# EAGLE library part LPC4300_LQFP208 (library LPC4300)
LQFP208 - SOT459-1 LQFP208: plastic low profile quad flat package; 208 leads; body 28 x 28 x 1.4 mm body + leads 30 x 30 mm Solderland (pads) 0.4 x 1.5 mm on corners (8 x) and 0.28 x 1.5 mm (200 x)
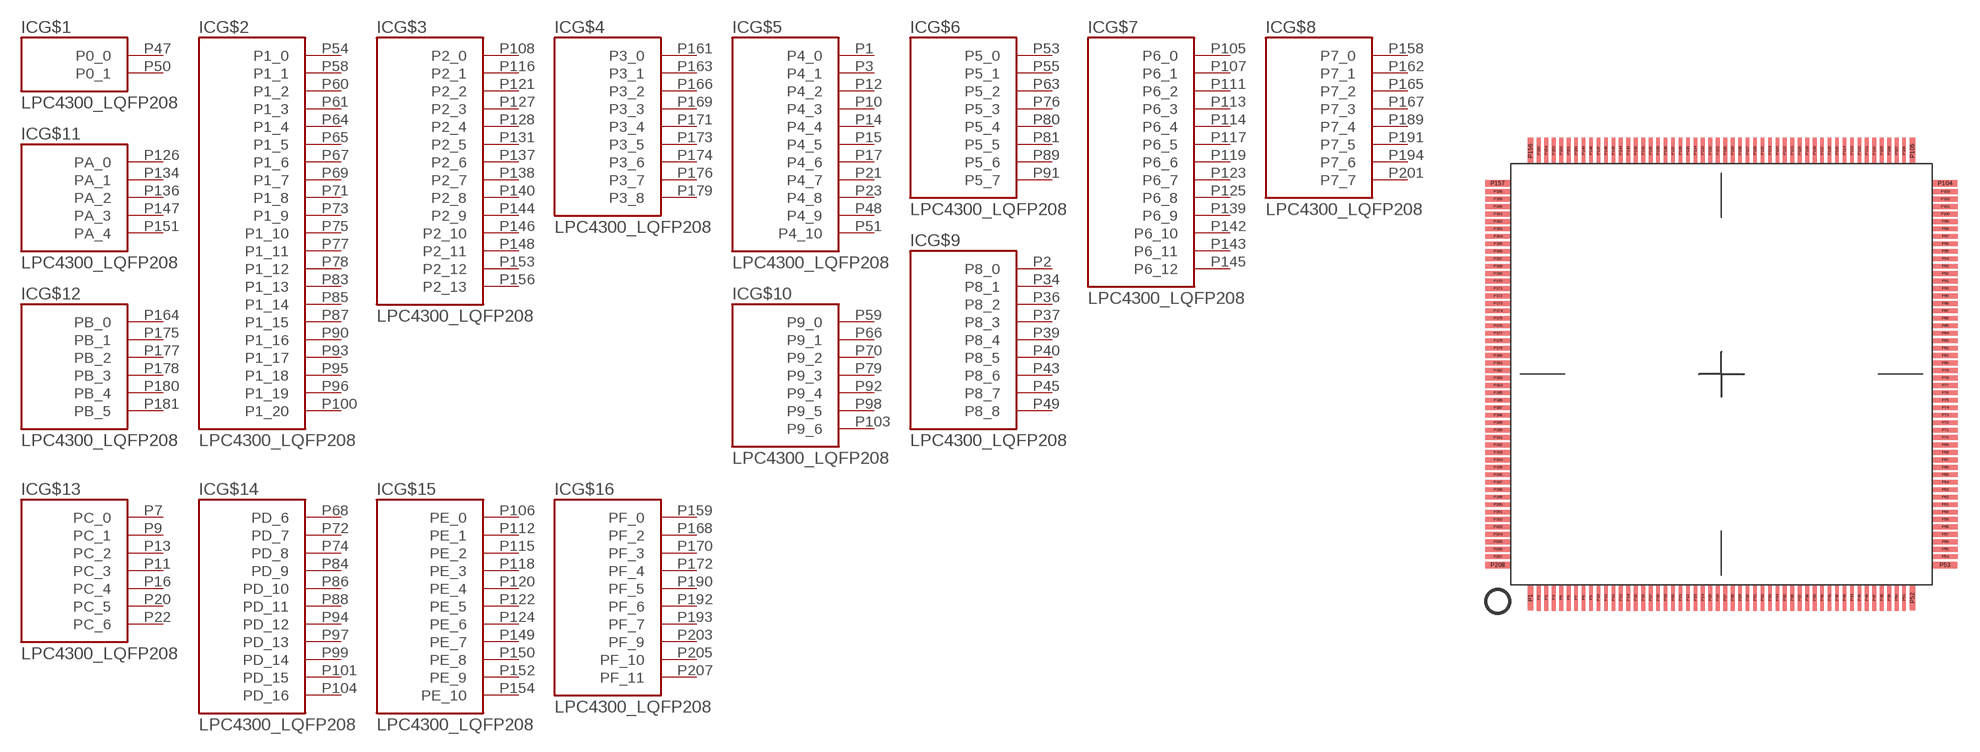
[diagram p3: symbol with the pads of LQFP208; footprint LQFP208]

Designator prefix IC; gates G$1=208_1_PORT0 G$2=208_2_PORT1 G$3=208_3_PORT2 G$4=208_4_PORT3 G$5=208_5_PORT4 G$6=208_6_PORT5 G$7=208_7_PORT6 G$8=208_8_PORT7 G$9=208_9_PORT8 G$10=208_10_PORT9 G$11=208_11_PORTA G$12=208_12_PORTB G$13=208_13_PORTC G$14=208_14_PORTD G$15=208_15_PORTE G$16=208_16_PORTF G$17=208_17_ANA G$18=208_18_RTC G$19=208_19_CLK G$20=208_20_DBUG G$21=208_21_I2C G$22=208_22_SUP G$23=208_23_USB

## LPC4300_LQFP208  [LQFP208]
P1  G$5:P4_0
P2  G$9:P8_0
P3  G$5:P4_1
P4  G$17:ADC1  in
P5  G$22:VSSIO1  sup
P6  G$22:VDDIO1  sup
P7  G$13:PC_0
P8  G$17:ADC0  in
P9  G$13:PC_1
P10  G$5:P4_3
P11  G$13:PC_3
P12  G$5:P4_2
P13  G$13:PC_2
P14  G$5:P4_4
P15  G$5:P4_5
P16  G$13:PC_4
P17  G$5:P4_6
P18  G$19:XTAL1  in
P19  G$19:XTAL2  out
P20  G$13:PC_5
P21  G$5:P4_7
P22  G$13:PC_6
P23  G$5:P4_8
P24  G$23:USB0_VDDA3V3_DRIVER
P25  G$23:USB0_VDDA3V3
P26  G$23:USB0_DP
P27  G$23:USB0_VSSA_TERM
P28  G$23:USB0_DM
P29  G$23:USB0_VBUS
P30  G$23:USB0_ID
P31  G$23:USB0_VSSA_REF
P32  G$23:USB0_RREF
P33  G$22:VDDREG5  sup
P34  G$9:P8_1
P35  G$20:TDI
P36  G$9:P8_2
P37  G$9:P8_3
P38  G$20:TCK
P39  G$9:P8_4
P40  G$9:P8_5
P41  G$20:DBGEN  in
P42  G$20:!TRST
P43  G$9:P8_6
P44  G$20:TMS
P45  G$9:P8_7
P46  G$20:TDO
P47  G$1:P0_0
P48  G$5:P4_9
P49  G$9:P8_8  sup
P50  G$1:P0_1
P51  G$5:P4_10
P52  G$22:VDDIO2  sup
P53  G$6:P5_0
P54  G$2:P1_0
P55  G$6:P5_1
P56  G$22:VSSIO2  sup
P57  G$22:VDDIO3  sup
P58  G$2:P1_1
P59  G$10:P9_0
P60  G$2:P1_2
P61  G$2:P1_3
P62  G$19:CLK0  out
P63  G$6:P5_2
P64  G$2:P1_4
P65  G$2:P1_5
P66  G$10:P9_1
P67  G$2:P1_6
P68  G$14:PD_6
P69  G$2:P1_7
P70  G$10:P9_2
P71  G$2:P1_8
P72  G$14:PD_7
P73  G$2:P1_9
P74  G$14:PD_8
P75  G$2:P1_10
P76  G$6:P5_3
P77  G$2:P1_11
P78  G$2:P1_12
P79  G$10:P9_3
P80  G$6:P5_4
P81  G$6:P5_5
P82  G$22:VDDREG4  sup
P83  G$2:P1_13
P84  G$14:PD_9
P85  G$2:P1_14
P86  G$14:PD_10
P87  G$2:P1_15
P88  G$14:PD_11
P89  G$6:P5_6
P90  G$2:P1_16
P91  G$6:P5_7
P92  G$10:P9_4
P93  G$2:P1_17
P94  G$14:PD_12
P95  G$2:P1_18
P96  G$2:P1_19
P97  G$14:PD_13
P98  G$10:P9_5
P99  G$14:PD_14
P100  G$2:P1_20
P101  G$14:PD_15
P102  G$22:VDDIO4  sup
P103  G$10:P9_6
P104  G$14:PD_16
P105  G$7:P6_0
P106  G$15:PE_0
P107  G$7:P6_1
P108  G$3:P2_0
P109  G$22:VSSIO3  sup
P110  G$22:VDDIO5  sup
P111  G$7:P6_2
P112  G$15:PE_1
P113  G$7:P6_3
P114  G$7:P6_4
P115  G$15:PE_2
P116  G$3:P2_1
P117  G$7:P6_5
P118  G$15:PE_3
P119  G$7:P6_6
P120  G$15:PE_4
P121  G$3:P2_2
P122  G$15:PE_5
P123  G$7:P6_7
P124  G$15:PE_6
P125  G$7:P6_8
P126  G$11:PA_0
P127  G$3:P2_3
P128  G$3:P2_4
P129  G$23:USB1_DP
P130  G$23:USB1_DM
P131  G$3:P2_5
P132  G$21:I2C0_SCL
P133  G$21:I2C0_SDA
P134  G$11:PA_1
P135  G$22:VDDREG1  sup
P136  G$11:PA_2
P137  G$3:P2_6
P138  G$3:P2_7
P139  G$7:P6_9
P140  G$3:P2_8
P141  G$19:CLK2  out
P142  G$7:P6_10
P143  G$7:P6_11
P144  G$3:P2_9
P145  G$7:P6_12
P146  G$3:P2_10
P147  G$11:PA_3
P148  G$3:P2_11
P149  G$15:PE_7
P150  G$15:PE_8
P151  G$11:PA_4
P152  G$15:PE_9
P153  G$3:P2_12
P154  G$15:PE_10
P155  G$22:VDDIO6  sup
P156  G$3:P2_13
P157  G$22:VSSIO4  sup
P158  G$8:P7_0
P159  G$16:PF_0
P160  G$22:VDDIO7  sup
P161  G$4:P3_0
P162  G$8:P7_1
P163  G$4:P3_1
P164  G$12:PB_0
P165  G$8:P7_2
P166  G$4:P3_2
P167  G$8:P7_3
P168  G$16:PF_2
P169  G$4:P3_3
P170  G$16:PF_3
P171  G$4:P3_4
P172  G$16:PF_4
P173  G$4:P3_5
P174  G$4:P3_6
P175  G$12:PB_1
P176  G$4:P3_7
P177  G$12:PB_2
P178  G$12:PB_3
P179  G$4:P3_8
P180  G$12:PB_4
P181  G$12:PB_5
P182  G$18:RTCX1  in
P183  G$18:RTCX2  out
P184  G$18:VBAT  pwr
P185  G$19:!RESET  in
P186  G$18:RTC_ALARM  out
P187  G$18:WAKEUP0  in
P188  G$22:VDDREG2  sup
P189  G$8:P7_4
P190  G$16:PF_5
P191  G$8:P7_5
P192  G$16:PF_6
P193  G$16:PF_7
P194  G$8:P7_6
P195  G$22:VDDREG3  sup
P196  G$17:VSSA  sup
P197  G$17:ADC7  in
P198  G$17:VDDA  sup
P199  G$17:ADC4  in
P200  G$17:ADC3  in
P201  G$8:P7_7
P202  G$22:VDDIO8  sup
P203  G$16:PF_9
P204  G$17:ADC6  in
P205  G$16:PF_10
P206  G$17:ADC2  in
P207  G$16:PF_11
P208  G$17:ADC5  in

## Footprint LQFP208 (pad centres in mm)
LQFP208 - SOT459-1 LQFP208: plastic low profile quad flat package; 208 leads; body 28 x 28 x 1.4 mm body + leads 30 x 30 mm Solderland (pads) 0.4 x 1.5 mm on corners (8 x) and 0.28 x 1.5 mm (200 x) .
smd 0.4 x 1.7: P1 -12.81,-15; P52 12.81,-15; P105 12.81,15; P156 -12.81,15
smd 0.28 x 1.7: P2 -12.25,-15; P3 -11.75,-15; P4 -11.25,-15; P5 -10.75,-15; P6 -10.25,-15; P7 -9.75,-15; P8 -9.25,-15; P9 -8.75,-15; P10 -8.25,-15; P11 -7.75,-15; P12 -7.25,-15; P13 -6.75,-15; P14 -6.25,-15; P15 -5.75,-15; P16 -5.25,-15; P17 -4.75,-15; P18 -4.25,-15; P19 -3.75,-15; P20 -3.25,-15; P21 -2.75,-15; P22 -2.25,-15; P23 -1.75,-15; P24 -1.25,-15; P25 -0.75,-15; P26 -0.25,-15; P27 0.25,-15; P28 0.75,-15; P29 1.25,-15; P30 1.75,-15; P31 2.25,-15; P32 2.75,-15; P33 3.25,-15; P34 3.75,-15; P35 4.25,-15; P36 4.75,-15; P37 5.25,-15; P38 5.75,-15; P39 6.25,-15; P40 6.75,-15; P41 7.25,-15; P42 7.75,-15; P43 8.25,-15; P44 8.75,-15; P45 9.25,-15; P46 9.75,-15; P47 10.25,-15; P48 10.75,-15; P49 11.25,-15; P50 11.75,-15; P51 12.25,-15; P106 12.25,15; P107 11.75,15; P108 11.25,15; P109 10.75,15; P110 10.25,15; P111 9.75,15; P112 9.25,15; P113 8.75,15; P114 8.25,15; P115 7.75,15; P116 7.25,15; P117 6.75,15; P118 6.25,15; P119 5.75,15; P120 5.25,15; P121 4.75,15; P122 4.25,15; P123 3.75,15; P124 3.25,15; P125 2.75,15; P126 2.25,15; P127 1.75,15; P128 1.25,15; P129 0.75,15; P130 0.25,15; P131 -0.25,15; P132 -0.75,15; P133 -1.25,15; P134 -1.75,15; P135 -2.25,15; P136 -2.75,15; P137 -3.25,15; P138 -3.75,15; P139 -4.25,15; P140 -4.75,15; P141 -5.25,15; P142 -5.75,15; P143 -6.25,15; P144 -6.75,15; P145 -7.25,15; P146 -7.75,15; P147 -8.25,15; P148 -8.75,15; P149 -9.25,15; P150 -9.75,15; P151 -10.25,15; P152 -10.75,15; P153 -11.25,15; P154 -11.75,15; P155 -12.25,15
smd 1.7 x 0.4: P53 15,-12.81; P104 15,12.81; P157 -15,12.81; P208 -15,-12.81
smd 1.7 x 0.28: P54 15,-12.25; P55 15,-11.75; P56 15,-11.25; P57 15,-10.75; P58 15,-10.25; P59 15,-9.75; P60 15,-9.25; P61 15,-8.75; P62 15,-8.25; P63 15,-7.75; P64 15,-7.25; P65 15,-6.75; P66 15,-6.25; P67 15,-5.75; P68 15,-5.25; P69 15,-4.75; P70 15,-4.25; P71 15,-3.75; P72 15,-3.25; P73 15,-2.75; P74 15,-2.25; P75 15,-1.75; P76 15,-1.25; P77 15,-0.75; P78 15,-0.25; P79 15,0.25; P80 15,0.75; P81 15,1.25; P82 15,1.75; P83 15,2.25; P84 15,2.75; P85 15,3.25; P86 15,3.75; P87 15,4.25; P88 15,4.75; P89 15,5.25; P90 15,5.75; P91 15,6.25; P92 15,6.75; P93 15,7.25; P94 15,7.75; P95 15,8.25; P96 15,8.75; P97 15,9.25; P98 15,9.75; P99 15,10.25; P100 15,10.75; P101 15,11.25; P102 15,11.75; P103 15,12.25; P158 -15,12.25; P159 -15,11.75; P160 -15,11.25; P161 -15,10.75; P162 -15,10.25; P163 -15,9.75; P164 -15,9.25; P165 -15,8.75; P166 -15,8.25; P167 -15,7.75; P168 -15,7.25; P169 -15,6.75; P170 -15,6.25; P171 -15,5.75; P172 -15,5.25; P173 -15,4.75; P174 -15,4.25; P175 -15,3.75; P176 -15,3.25; P177 -15,2.75; P178 -15,2.25; P179 -15,1.75; P180 -15,1.25; P181 -15,0.75; P182 -15,0.25; P183 -15,-0.25; P184 -15,-0.75; P185 -15,-1.25; P186 -15,-1.75; P187 -15,-2.25; P188 -15,-2.75; P189 -15,-3.25; P190 -15,-3.75; P191 -15,-4.25; P192 -15,-4.75; P193 -15,-5.25; P194 -15,-5.75; P195 -15,-6.25; P196 -15,-6.75; P197 -15,-7.25; P198 -15,-7.75; P199 -15,-8.25; P200 -15,-8.75; P201 -15,-9.25; P202 -15,-9.75; P203 -15,-10.25; P204 -15,-10.75; P205 -15,-11.25; P206 -15,-11.75; P207 -15,-12.25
